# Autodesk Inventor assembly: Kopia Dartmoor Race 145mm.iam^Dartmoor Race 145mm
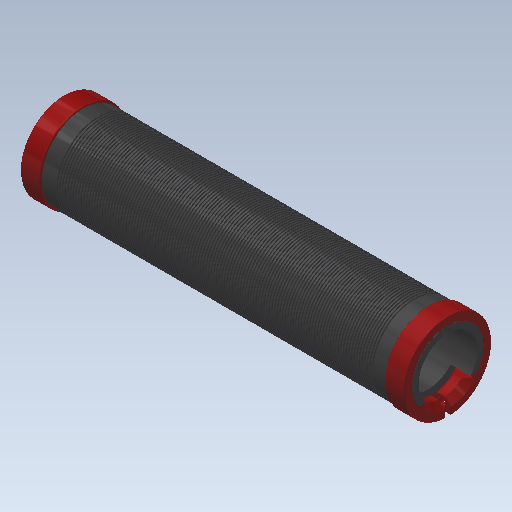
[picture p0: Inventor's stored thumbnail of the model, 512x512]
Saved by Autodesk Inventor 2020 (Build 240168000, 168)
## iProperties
Created: 2017-10
Part Number: Kopia Dartmoor Race 145mm.iam^Dartmoor Race 145mm
Material: Ogólny
Document SubType Name: Assembly
Designer: Tomasz
Sending System: SolidWorks 2017
Last Author: Tomasz
Last Saved: 2017-10-01
Author: Tomasz
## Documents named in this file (4)
- C:\Users\bruno\Documents\1-Cours-2020-21\1STI2D-2020-21\IT\6. Antivol\Inventor-Antivol\INVENTOR 2018_Steel Hardtail B+\Kopia Dartmoor Race 145mm.iam^Dartmoor Race 145mm.iam
- C:\Users\bruno\Documents\1-Cours-2020-21\1STI2D-2020-21\IT\6. Antivol\Inventor-Antivol\INVENTOR 2018_Steel Hardtail B+\Kopia Korpus chwytu.ipt^Kopia Dartmoor Race 145mm.iam_Dartmoor Race 145mm.ipt
- C:\Users\bruno\Documents\1-Cours-2020-21\1STI2D-2020-21\IT\6. Antivol\Inventor-Antivol\INVENTOR 2018_Steel Hardtail B+\Kopia obejma.ipt^Kopia Dartmoor Race 145mm.iam_Dartmoor Race 145mm.ipt
- C:\Users\bruno\Documents\1-Cours-2020-21\1STI2D-2020-21\IT\6. Antivol\Inventor-Antivol\INVENTOR 2018_Steel Hardtail B+\Kopia ISO 4762 - M3 x 10ISO.ipt^Kopia Dartmoor Race 145mm.iam_Dartmoor Race 145mm.ipt
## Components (5 placed, 3 different names)
1. Kopia Korpus chwytu.ipt^Kopia Dartmoor Race 145mm.iam_Dartmoor Race 145mm:1
2. Kopia obejma.ipt^Kopia Dartmoor Race 145mm.iam_Dartmoor Race 145mm:1
3. Kopia obejma.ipt^Kopia Dartmoor Race 145mm.iam_Dartmoor Race 145mm:2
4. Kopia ISO 4762 - M3 x 10ISO.ipt^Kopia Dartmoor Race 145mm.iam_Dartmoor Race 145mm:1
5. Kopia ISO 4762 - M3 x 10ISO.ipt^Kopia Dartmoor Race 145mm.iam_Dartmoor Race 145mm:2
